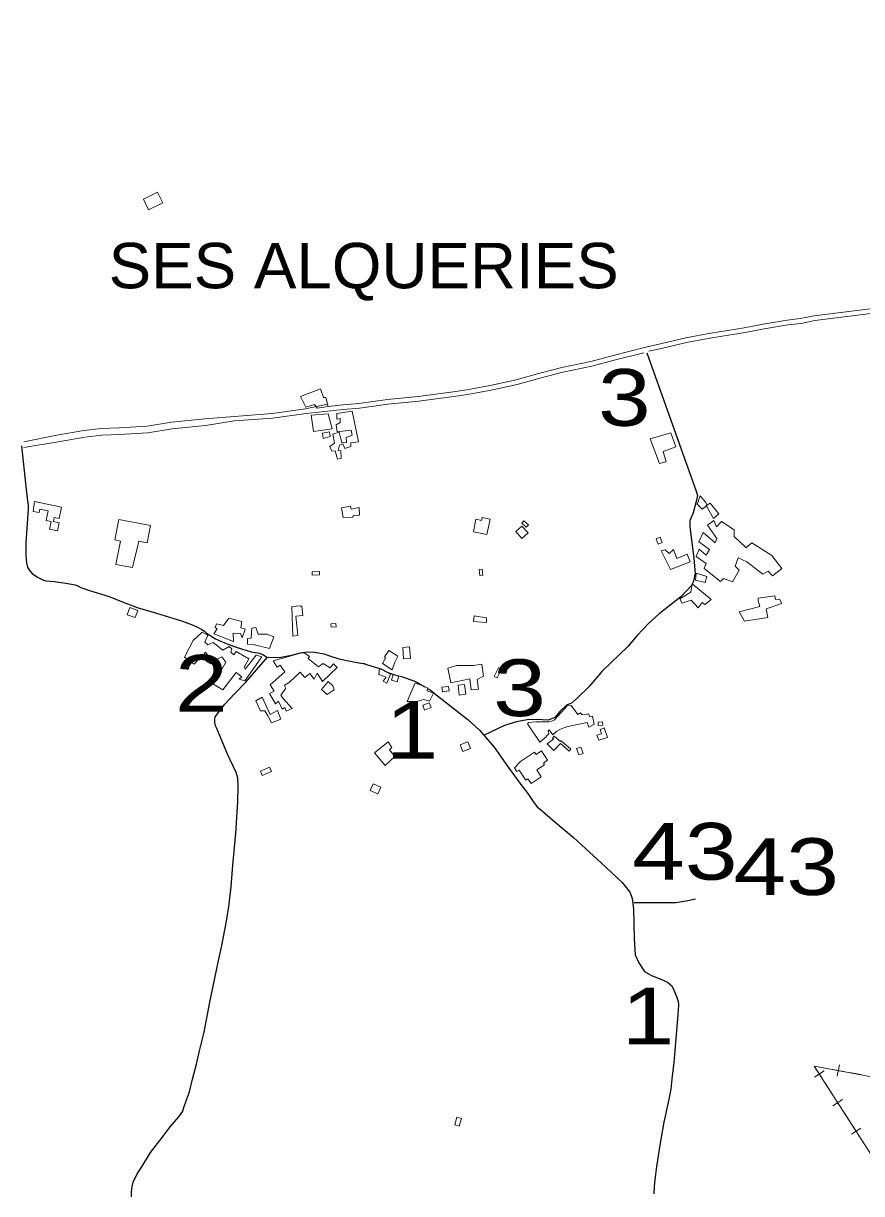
# Model space of a CAD drawing. Extents: x 476989 to 498418, y 4381813 to 4416555.
# Drawn here: x 486413 to 487152, y 4386800 to 4387830 of the extents above; entities that cross this region are included whole.
import ezdxf
from ezdxf.enums import TextEntityAlignment as Align

# ---------------------------------------------------------------- set-up
doc = ezdxf.new("R2010")
doc.units = 0
doc.header["$LTSCALE"] = 20
doc.linetypes.add('MEDIUM_DASHED', pattern=[4.5, 3, -1.5])
for name, color, linetype, lineweight in [('13', 7, 'Continuous', 13), ('34', 7, 'Continuous', 13), ('36', 7, 'Continuous', 13), ('47', 7, 'Continuous', 13), ('48', 7, 'MEDIUM_DASHED', 13), ('6', 7, 'Continuous', 25)]:
    doc.layers.add(name, color=color, linetype=linetype, lineweight=lineweight)
doc.layers.add('7', color=7, linetype='Continuous')

msp = doc.modelspace()

# ---------------------------------------------------------------- linework, layer by layer
at = {"layer": '34'}
for p, q in [((487118.7, 4386907.72), (487110.3, 4386902.31)), ((487121.49, 4386909.88), (487111.65, 4386911.69)), ((487111.79, 4386909.22), (487117.21, 4386900.81)), ((487136.24, 4386907.16), (487126.4, 4386908.97)), ((487130.41, 4386903.15), (487132.23, 4386912.98)), ((487150.98, 4386904.43), (487141.14, 4386906.25)), ((487119.92, 4386896.61), (487125.33, 4386888.2)), ((487134.95, 4386882.51), (487126.54, 4386877.1)), ((487128.04, 4386884.01), (487133.45, 4386875.6)), ((487136.16, 4386871.4), (487141.58, 4386862.99)), ((487151.19, 4386857.3), (487142.79, 4386851.89)), ((487144.28, 4386858.8), (487149.7, 4386850.39))]:
    msp.add_line(p, q, dxfattribs=at)
msp.add_lwpolyline([(486520.9, 4388755.72), (486603, 4388633), (486612, 4388581), (486746, 4388393), (486776, 4388338), (486812, 4388290), (486879, 4388250), (487017, 4388189), (487152, 4388148), (487234, 4388140), (487360, 4387899), (487497, 4387717), (487531, 4387660), (487608, 4387440), (487634, 4387181), (487675, 4387065), (487547, 4387001), (487350, 4386921), (487175, 4386900), (487110, 4386912), (487380, 4386493), (487280.6, 4386441.97)], dxfattribs=at)
at = {"layer": '36'}
for points in [[(486964.24, 4387541.72), (486976.62, 4387544.44), (486997.64, 4387549.32), (487019.8, 4387553.44), (487049.13, 4387558.2), (487065.84, 4387561.49), (487086.71, 4387564.87), (487098.48, 4387566.27), (487110.55, 4387568.8), (487159.87, 4387575), (487190.84, 4387579.06), (487223.09, 4387583.7), (487249.79, 4387587.82), (487273.23, 4387590.72), (487282.06, 4387591.19), (487293.97, 4387593.33), (487302.49, 4387595.71), (487317.85, 4387602.66), (487349.41, 4387615.35), (487395.22, 4387635.1), (487449.89, 4387659.15), (487513.35, 4387686.84), (487513.66, 4387686.96)], [(486681.81, 4387493.08), (486694.64, 4387494.43), (486708.83, 4387495.72), (486733.93, 4387499.19), (486761.2, 4387501.8), (486789.75, 4387505.79), (486803.91, 4387507.68), (486824.62, 4387511.62), (486847.35, 4387516.42), (486868.27, 4387522.32), (486887.64, 4387527.27), (486913.13, 4387532.74), (486932.76, 4387537.91), (486960.47, 4387544.96), (486975.67, 4387548.51), (486996.79, 4387553.41), (487019.08, 4387557.56), (487048.39, 4387562.31), (487065.1, 4387565.6), (487086.13, 4387569.01), (487097.8, 4387570.4), (487109.95, 4387572.95), (487159.3, 4387579.14)], [(486598.9, 4387480.47), (486632.81, 4387482.84), (486662.41, 4387486.84), (486695.05, 4387490.27), (486709.31, 4387491.57), (486734.42, 4387495.04), (486761.69, 4387497.65), (486790.31, 4387501.65), (486804.58, 4387503.55), (486825.44, 4387507.52), (486848.35, 4387512.36), (486869.35, 4387518.28), (486888.6, 4387523.19), (486914.1, 4387528.67), (486933.81, 4387533.87), (486959.88, 4387540.27)], [(486632.38, 4387487), (486661.92, 4387490.99), (486681.28, 4387495)], [(486413.56, 4387461.76), (486442.85, 4387467.63), (486466.63, 4387471.94), (486482.05, 4387473.6), (486497.67, 4387474.12), (486522.37, 4387475.65), (486543.65, 4387479.24), (486573.11, 4387482.2), (486632.38, 4387487)], [(486413.64, 4387456.96), (486443.84, 4387461.83), (486467.47, 4387466.12), (486482.46, 4387467.73), (486497.95, 4387468.25), (486523.04, 4387469.8), (486544.43, 4387473.41), (486573.69, 4387476.35), (486598.9, 4387480.47)]]:
    msp.add_lwpolyline(points, dxfattribs=at)
at = {"layer": '47'}
for points in [[(486681.79, 4387493.07), (486672.16, 4387491.55), (486669.88, 4387494.66), (486662.05, 4387492.45), (486657.31, 4387501.97), (486675.11, 4387508.62), (486677.55, 4387500.93), (486679.72, 4387500.83)], [(486681.77, 4387486.46), (486685.26, 4387473.28), (486668.94, 4387470.89), (486666.9, 4387485.4)], [(486702.81, 4387488.86), (486689.51, 4387486.95), (486689.28, 4387481.93), (486692.44, 4387482.41), (486692.39, 4387478.88), (486688.91, 4387476.98), (486689.65, 4387470.82), (486702.2, 4387472.21), (486702.81, 4387467.63), (486697.75, 4387465.6), (486697.92, 4387461.17), (486693.79, 4387460.93), (486691.37, 4387470.42), (486686.02, 4387468.54), (486687.4, 4387460.65), (486683.39, 4387457.85), (486684.98, 4387453.7), (486687.83, 4387454.11), (486690.05, 4387446.65), (486693.36, 4387447.2), (486693.01, 4387453.96), (486690.46, 4387454.15), (486691.88, 4387458.93), (486694.82, 4387460.09), (486696.34, 4387455.94), (486701.85, 4387457.89), (486701.89, 4387461.04), (486708.65, 4387461.77)], [(486682.82, 4387470.77), (486676.87, 4387469.5), (486677.41, 4387464.84), (486683.66, 4387466.48)], [(486988.11, 4387457.61), (486976.94, 4387453.27), (486979.74, 4387444.23), (486973.64, 4387442.81), (486965.47, 4387464.47), (486983.7, 4387469.68)], [(487009.7, 4387414.31), (487006.96, 4387406.84), (487011.33, 4387402.58), (487015.65, 4387405.67), (487014.64, 4387408.39)], [(486423.14, 4387409.21), (486446.93, 4387404.29), (486444.89, 4387394.45), (486440.49, 4387395.32), (486439.77, 4387391.68), (486444.84, 4387390.63), (486443.34, 4387383.4), (486436.27, 4387384.85), (486437.68, 4387391.77), (486433.34, 4387392.62), (486435, 4387401.12), (486427.82, 4387402.49), (486427.27, 4387399.61), (486421.83, 4387400.62)], [(486693.57, 4387403.76), (486695.02, 4387395.26), (486703.65, 4387395.43), (486703.9, 4387397), (486709.38, 4387397.3), (486709.03, 4387403.98), (486701.95, 4387402.51), (486701.39, 4387405.29)], [(487014.75, 4387405.91), (487021.42, 4387394.48), (487025.9, 4387398.47), (487018.31, 4387407.96)], [(486509.27, 4387351.09), (486494.76, 4387353.93), (486498.79, 4387374.52), (486493.86, 4387375.47), (486497.34, 4387393.57), (486525.22, 4387388.19), (486522.26, 4387372.89), (486514.98, 4387374.26)], [(486821.62, 4387380.39), (486809.87, 4387382.65), (486811.99, 4387393.69), (486816.99, 4387392.71), (486817.49, 4387395.28), (486824.65, 4387393.85)], [(486856.38, 4387386.79), (486852.4, 4387390.34), (486854.28, 4387392.45), (486858.26, 4387388.9)], [(487081.64, 4387350.32), (487072.72, 4387361.63), (487055.18, 4387372.99), (487049.93, 4387368.41), (487049.87, 4387368.86), (487039.57, 4387378.61), (487039.66, 4387384.39), (487028.28, 4387391.83), (487024.09, 4387387.16), (487021.62, 4387392.6), (487016.01, 4387388.56), (487024.24, 4387376.66), (487022.69, 4387372.93), (487012.16, 4387382.01), (487008.44, 4387373.73), (487017.65, 4387367.07), (487014.8, 4387362.09), (487008.57, 4387367.2), (487006, 4387360.86), (487014.77, 4387354.81), (487012.98, 4387350.33), (487027.45, 4387338.79), (487030.26, 4387341.53), (487038.03, 4387338.57), (487043.8, 4387348.84), (487040.32, 4387352.34), (487043.13, 4387359.73), (487050.73, 4387356.09), (487064.68, 4387345.31), (487069.37, 4387347.95), (487073.37, 4387343.84)], [(486852.49, 4387387.75), (486857.88, 4387381.59), (486852.48, 4387376.87), (486847.09, 4387383.03)], [(486970.73, 4387376.37), (486972.49, 4387371.88), (486976.09, 4387373.29), (486974.33, 4387377.78)], [(487000.61, 4387356.21), (486983.33, 4387349.33), (486975.16, 4387365.73), (486978.78, 4387366.8), (486982.1, 4387363.38), (486986.06, 4387367.15), (486988.87, 4387359.23), (486998.08, 4387362.92), (486998.08, 4387362.92)], [(486817.5, 4387349.83), (486818.08, 4387344.44), (486815.47, 4387344.16), (486814.89, 4387349.55)], [(486674.26, 4387344.83), (486667.77, 4387344.47), (486667.62, 4387347.25), (486674.11, 4387347.61)], [(487014.08, 4387337.93), (487005.48, 4387340.08), (487006.17, 4387346.3), (487015.58, 4387343.24)], [(487019.27, 4387323), (487002.58, 4387336.67), (487001.35, 4387329.49), (486991.66, 4387323.47), (486993.71, 4387319.69), (487001.63, 4387322.5), (487007.76, 4387315.81), (487011.43, 4387320.26), (487013.8, 4387318.5)], [(486650.75, 4387290.61), (486649.85, 4387316.81), (486657.48, 4387317.36), (486657.49, 4387317.1), (486658.65, 4387317.22), (486659.5, 4387308.99), (486653.39, 4387308.4), (486655.04, 4387291.23)], [(487069.09, 4387307.28), (487048.56, 4387303.82), (487043.88, 4387312.22), (487062.18, 4387316.98), (487060.6, 4387321.96), (487060.63, 4387324.29), (487075.29, 4387326.33), (487076, 4387323.01), (487079.53, 4387323.26), (487081.65, 4387319.41), (487067.7, 4387314.8)], [(486506.97, 4387315.93), (486514.07, 4387313.45), (486511.87, 4387307.16), (486504.77, 4387309.64)], [(486810.46, 4387308.66), (486821.17, 4387306.93), (486821.18, 4387302.65), (486809.94, 4387303.72)], [(486598.24, 4387286.11), (486581.15, 4387292.66), (486583.99, 4387297.05), (486582.13, 4387298.2), (486583.38, 4387301.63), (486589.66, 4387300.12), (486594.18, 4387306.58), (486605.77, 4387303.64), (486604.94, 4387298.1), (486608.67, 4387296.99), (486605.93, 4387289.23), (486604.64, 4387293.07), (486598.12, 4387293.39)], [(486629.96, 4387279.81), (486615.6, 4387283.24), (486610.81, 4387283.68), (486610.73, 4387288.64), (486613.96, 4387288.96), (486614.39, 4387297.74), (486618.07, 4387298.21), (486620.09, 4387292.55), (486627.82, 4387292.37), (486634.01, 4387290.1)], [(486688.69, 4387298.92), (486684.37, 4387298.62), (486684.15, 4387301.69), (486688.47, 4387301.99)], [(486608.39, 4387251.38), (486623.48, 4387272.54), (486618.24, 4387273.82), (486608.76, 4387261.5), (486607.66, 4387263.32), (486611.75, 4387270.61), (486600.74, 4387277.3), (486598.59, 4387274.33), (486596.07, 4387276.61), (486596.94, 4387279.6), (486594.57, 4387281.59), (486588.97, 4387278.37), (486580.44, 4387285.09), (486575.83, 4387283.21), (486573.24, 4387285.5), (486575.65, 4387291.69), (486570.74, 4387294.09), (486562.91, 4387286.99), (486555.12, 4387272.32), (486563.66, 4387265.97), (486569.91, 4387273.24), (486570.72, 4387272.18), (486573.71, 4387276.63), (486576.14, 4387273.45), (486573.68, 4387269.36), (486578.29, 4387266.36), (486582.32, 4387269.46), (486588.06, 4387272.38), (486591.67, 4387267.67), (486580.81, 4387248.47), (486588.92, 4387243.48), (486600.69, 4387258.61), (486605.82, 4387254.94), (486603.39, 4387252.72)], [(486738.05, 4387261.15), (486729.72, 4387266.75), (486732.19, 4387271.44), (486731.46, 4387272.57), (486735.21, 4387278.07), (486743.24, 4387273.08), (486740.47, 4387267.87)], [(486753.34, 4387281.26), (486754.19, 4387271.17), (486748.31, 4387270.68), (486747.46, 4387280.77)], [(486689.6, 4387262.97), (486676.74, 4387250.7), (486672.05, 4387258.04), (486669.34, 4387252.83), (486665.59, 4387257.68), (486661.19, 4387254.3), (486657.12, 4387258.86), (486647.85, 4387250.21), (486643.31, 4387247.5), (486643.67, 4387246.67), (486644.47, 4387244.86), (486640.18, 4387238.76), (486641.79, 4387236.04), (486650.14, 4387226.99), (486644.78, 4387224.67), (486643.48, 4387227.99), (486641.13, 4387226.44), (486638.15, 4387233.39), (486635.34, 4387231.11), (486630, 4387240.34), (486634.08, 4387242.3), (486630.55, 4387247.83), (486643.47, 4387259.35), (486639.43, 4387265.26), (486636.78, 4387263.35), (486633.33, 4387269.1), (486658.49, 4387275.95), (486661.12, 4387275.83), (486665.28, 4387272.85), (486664.05, 4387271.14), (486673.33, 4387263.73), (486677.42, 4387266.74), (486683.6, 4387262.9), (486686.35, 4387266.39)], [(486806.59, 4387253.19), (486789.73, 4387249.68), (486787.14, 4387262.62), (486795.2, 4387264.76), (486809.98, 4387264.77), (486817.05, 4387266.02), (486818.71, 4387255.57), (486813.04, 4387252.65), (486814.34, 4387244.15), (486807.73, 4387243.57)], [(486727.03, 4387262.13), (486736.71, 4387257.19), (486733.6, 4387249.28), (486730.17, 4387250.98), (486732.78, 4387254.7), (486726.51, 4387257.04)], [(486742.69, 4387250.35), (486737.52, 4387251.81), (486738.96, 4387256.93), (486744.13, 4387255.47)], [(486834.4, 4387261.64), (486830.63, 4387253.99), (486828.15, 4387255.21), (486831.92, 4387262.86)], [(486681.92, 4387250.7), (486675.89, 4387243.58), (486681.01, 4387239.46), (486687.14, 4387243.57), (486685.99, 4387247.04)], [(486758.36, 4387249.45), (486769.41, 4387245.09), (486768.92, 4387242.62), (486774.67, 4387240.36), (486771.04, 4387233.59), (486766.11, 4387234.86), (486759.93, 4387233.15), (486751.53, 4387233.27)], [(486788.28, 4387242.57), (486782.54, 4387241.81), (486782.02, 4387245.74), (486787.76, 4387246.5)], [(486797.31, 4387238.84), (486796.27, 4387247.46), (486802.02, 4387248.15), (486803.06, 4387239.53)], [(486617.97, 4387233.61), (486622.2, 4387225.07), (486626.1, 4387225.01), (486628.51, 4387220.4), (486628.66, 4387220.4), (486631.73, 4387214.42), (486640.02, 4387217.53), (486637.28, 4387225.22), (486630.7, 4387221.57), (486623.57, 4387236.9)], [(486770.8, 4387232.09), (486765.12, 4387229.83), (486766.8, 4387225.62), (486772.48, 4387227.88)], [(486868.22, 4387197.45), (486857.35, 4387213.44), (486858.19, 4387214.78), (486864.88, 4387215.21), (486871.55, 4387215.12), (486876.13, 4387215.27), (486876.51, 4387215.34), (486878.54, 4387215.84), (486879.44, 4387216.05), (486881.26, 4387217), (486892.46, 4387229.22), (486895.77, 4387229.7), (486901.66, 4387221.81), (486904.08, 4387223.13), (486905.64, 4387221.53), (486908.56, 4387221.56), (486910.07, 4387221.92), (486911.05, 4387222.43), (486912.36, 4387219.63), (486914.7, 4387220.2), (486916.17, 4387213.05), (486911.56, 4387210.56), (486910.04, 4387214.71), (486896.95, 4387212.12), (486892.2, 4387210.84), (486891.52, 4387210.63), (486890.92, 4387210.56), (486887.98, 4387209.48), (486886.39, 4387208.75), (486883.29, 4387206.99), (486879.8, 4387203.89), (486876.55, 4387208.06), (486875.64, 4387207.33), (486876.21, 4387204.77), (486873.77, 4387202.48), (486874.07, 4387202.25)], [(486919.83, 4387211.95), (486923.66, 4387212.18), (486923.48, 4387215.12), (486919.65, 4387214.89)], [(486920.17, 4387198.96), (486927.86, 4387201.55), (486925.07, 4387209.82), (486921.31, 4387208.57), (486922.6, 4387204.66), (486918.63, 4387203.36)], [(486740.48, 4387184.58), (486735.69, 4387190.72), (486737.89, 4387192.57), (486734.51, 4387197.57), (486722.74, 4387187.98), (486732.04, 4387176.89)], [(486804.97, 4387197.53), (486807.29, 4387191.65), (486800.49, 4387188.97), (486798.17, 4387194.85)], [(486874.8, 4387195.93), (486880.65, 4387190.07), (486884.2, 4387193.62), (486884.1, 4387193.71), (486886.41, 4387196.28), (486894.11, 4387189.35), (486895.63, 4387191.04), (486887.19, 4387198.61), (486886.47, 4387197.82), (486881.06, 4387202.73), (486879.38, 4387200.88), (486880.32, 4387200.01)], [(486851.24, 4387180.36), (486863.52, 4387188.59), (486864.92, 4387186.48), (486869.68, 4387189.65), (486875.18, 4387181.39), (486871.42, 4387178.9), (486872.43, 4387177.36), (486865.55, 4387172.85), (486869.53, 4387166.76), (486860.55, 4387160.89), (486857.85, 4387165.01), (486855.95, 4387163.76), (486850.02, 4387172.75), (486847.96, 4387171.41), (486845.86, 4387174.63)], [(486900.71, 4387191.74), (486902.59, 4387186.12), (486906.35, 4387187.38), (486904.47, 4387193)], [(486630.19, 4387175.2), (486622.2, 4387171.67), (486623.78, 4387168.09), (486631.77, 4387171.62)], [(486725.45, 4387151.85), (486718.86, 4387154.86), (486721.52, 4387160.69), (486728.11, 4387157.68)]]:
    msp.add_lwpolyline(points, close=True, dxfattribs=at)
at = {"layer": '48'}
for points in [[(486531.5, 4387681.91), (486518.99, 4387675.77), (486523.62, 4387666.34), (486536.13, 4387672.48)], [(486795.28, 4386866.99), (486793.41, 4386860.13), (486797.27, 4386859.08), (486799.14, 4386865.94)]]:
    msp.add_lwpolyline(points, close=True, dxfattribs=at)
at = {"layer": '6'}
msp.add_line((486815.26, 4387207.87), (486827.96, 4387192.96), dxfattribs=at)
for points in [[(486962.42, 4387540.27), (487005.9, 4387418.31), (487007.28, 4387414.58), (487005.99, 4387409.23), (487003.38, 4387399.43), (487002.36, 4387396.43), (487001.65, 4387395.16), (487001.2, 4387394.35), (487000.89, 4387393.54), (487000.51, 4387392.28), (487000.42, 4387391.62), (487000.4, 4387390.21), (487000.5, 4387386.99), (487003.86, 4387359.55), (487005.09, 4387345.63), (487004.67, 4387343.51), (487003.95, 4387340.29), (487003.31, 4387338.25), (487002, 4387335.41), (486997.18, 4387330.36), (486992.38, 4387325.46), (486973.32, 4387310.35), (486963.98, 4387301.94), (486954.08, 4387291.21), (486945.75, 4387281.5), (486923.23, 4387259.91), (486911.64, 4387246.42), (486901.28, 4387235.99), (486896.18, 4387231.77)], [(486411.61, 4387458.24), (486415.3, 4387422.43), (486416.72, 4387412.28), (486417.46, 4387406.2), (486417.33, 4387402.54), (486416.99, 4387394.22), (486415.48, 4387372.78), (486415.33, 4387362.26), (486415.97, 4387354.88), (486416.47, 4387352.52), (486417.3, 4387350.83), (486419.05, 4387348.22), (486421.07, 4387345.87), (486425.78, 4387342.62), (486428.02, 4387341.52), (486430.46, 4387340.43), (486433.13, 4387339.5), (486440.42, 4387338.79), (486450.6, 4387337.38), (486458.96, 4387335.83), (486461.08, 4387334.99), (486463.79, 4387333.66), (486471.49, 4387330.85), (486488.68, 4387325.72), (486499.63, 4387321.14), (486513.37, 4387315.84), (486530.49, 4387310.87), (486553.35, 4387303.94), (486562.89, 4387300.43), (486567.35, 4387298.34), (486569.2, 4387297.27), (486570.62, 4387296.51), (486572.68, 4387295.06), (486574.6, 4387293.23)], [(486574.6, 4387293.23), (486582.62, 4387288.43), (486590.34, 4387284.71), (486600.7, 4387280.94), (486613.89, 4387276.82), (486621.12, 4387275.61), (486624.29, 4387274.43), (486628.31, 4387271.95)], [(486628.9, 4387272.11), (486638.48, 4387271.93), (486650.95, 4387274.12), (486657.1, 4387276.06), (486663.18, 4387277.02), (486669.74, 4387276.52), (486678.26, 4387275.12), (486683.99, 4387273.21), (486690.31, 4387270.94), (486699.7, 4387269.09), (486710.54, 4387267.04), (486713.02, 4387266.69), (486713.92, 4387266.53), (486714.59, 4387266.16), (486720.23, 4387264.18), (486728.33, 4387261.91), (486734.39, 4387258.65), (486740.44, 4387256.54)], [(486508.47, 4386796.71), (486508.54, 4386801.18), (486508.95, 4386805.87), (486509.96, 4386809.7), (486513.59, 4386817), (486517.47, 4386823.37), (486525.21, 4386835.78), (486535.57, 4386849.15), (486542.53, 4386858.46), (486550.1, 4386867.13), (486553.64, 4386872.31), (486554.7, 4386875.55), (486557.07, 4386882.23), (486559.57, 4386889.33), (486562.24, 4386900.36), (486565.72, 4386913.63), (486568.44, 4386925.51), (486572.63, 4386941.95), (486577.49, 4386968.25), (486584.52, 4387002.01), (486588.12, 4387018.18), (486592.09, 4387039.77), (486594.27, 4387052.64), (486596.22, 4387069.83), (486597.85, 4387089.12), (486600.42, 4387116.95), (486602.31, 4387144.73), (486602.51, 4387158.7), (486602.12, 4387165.54), (486600.59, 4387170.92), (486600.46, 4387171.2), (486593.21, 4387186.85), (486583.65, 4387209.28), (486582.41, 4387211.77), (486581.87, 4387214.56), (486581.79, 4387217.25), (486582.34, 4387219.68), (486590.6, 4387230.84), (486599.3, 4387239.8), (486609.37, 4387250.12), (486628.41, 4387272.11)], [(486741.42, 4387256.25), (486746.47, 4387255.19), (486749.97, 4387254.04), (486758.67, 4387250.65), (486765.42, 4387247.08), (486766.97, 4387246.15)], [(486769.4, 4387244.7), (486771.63, 4387243.37), (486777.04, 4387239.11), (486782.02, 4387235.2), (486805.26, 4387217.13), (486815.26, 4387207.87)], [(486896.18, 4387231.77), (486891.75, 4387230.01), (486886.29, 4387224.76), (486881.42, 4387219.11), (486875.57, 4387216.78), (486865.44, 4387217.17), (486857.06, 4387216.97), (486847.71, 4387215.22), (486837.18, 4387212.11), (486819.25, 4387203.55)], [(486827.96, 4387192.96), (486840.26, 4387175.44), (486852.39, 4387158.74), (486857.7, 4387152), (486860.52, 4387147.59), (486862.96, 4387144.22), (486865.82, 4387140.44), (486870.56, 4387136.44), (486879.61, 4387128.5), (486897.89, 4387113.26), (486926.12, 4387087.48), (486940.93, 4387073.82), (486944.75, 4387069.02), (486947.51, 4387065.21), (486948.41, 4387063.27), (486948.98, 4387061.46), (486949.78, 4387059.74), (486950.89, 4387050.52), (486951.42, 4387024.29), (486952.31, 4387010.12), (486955.39, 4387002.81), (486960.38, 4386995.17), (486966.75, 4386991.88), (486976.24, 4386987.87), (486980.83, 4386985.8), (486984.46, 4386982.61), (486986.33, 4386978.92), (486988.67, 4386973.34), (486990.07, 4386968.73), (486990.35, 4386966.24), (486990.34, 4386965.73), (486989.85, 4386957.54), (486986.32, 4386914.8), (486984.82, 4386903.45), (486983.61, 4386891.79), (486981.37, 4386879.94), (486977.67, 4386862.56), (486974.46, 4386844.13), (486971.23, 4386823.55), (486969.53, 4386811.81), (486969.07, 4386806.08), (486968.75, 4386799.56)], [(486951.44, 4387056.08), (486988.25, 4387056.08), (486998.77, 4387057.99), (487005.46, 4387059.42)]]:
    msp.add_lwpolyline(points, dxfattribs=at)

# ---------------------------------------------------------------- texts
at = {"layer": '13', "width": 1.25}
for s, p in [('3', (486942.77, 4387475.99)), ('2', (486570.08, 4387224.13)), ('3', (486850.42, 4387220.28)), ('43', (486996.07, 4387076.2)), ('43', (487085.41, 4387062.68)), ('1', (486963.59, 4386931.1))]:
    msp.add_text(s, height=50, dxfattribs=at).set_placement(p, align=Align.CENTER)
at = {"layer": '6', "width": 1.25}
msp.add_text('1', height=50, dxfattribs=at).set_placement((486755.68, 4387182.92), align=Align.CENTER)
at = {"layer": '7', "width": 1.05}
msp.add_text('SES ALQUERIES', height=40, dxfattribs=at).set_placement((486713.08, 4387597.17), align=Align.CENTER)

doc.saveas('drawing.dxf')
